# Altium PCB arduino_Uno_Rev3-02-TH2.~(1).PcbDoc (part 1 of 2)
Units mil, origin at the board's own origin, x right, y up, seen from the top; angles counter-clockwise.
Board outline 3492.03 x 2110.03 mil, 2 copper layers (Top Layer, Bottom Layer); 62 components, 73 nets, 317 pads, 77 vias.
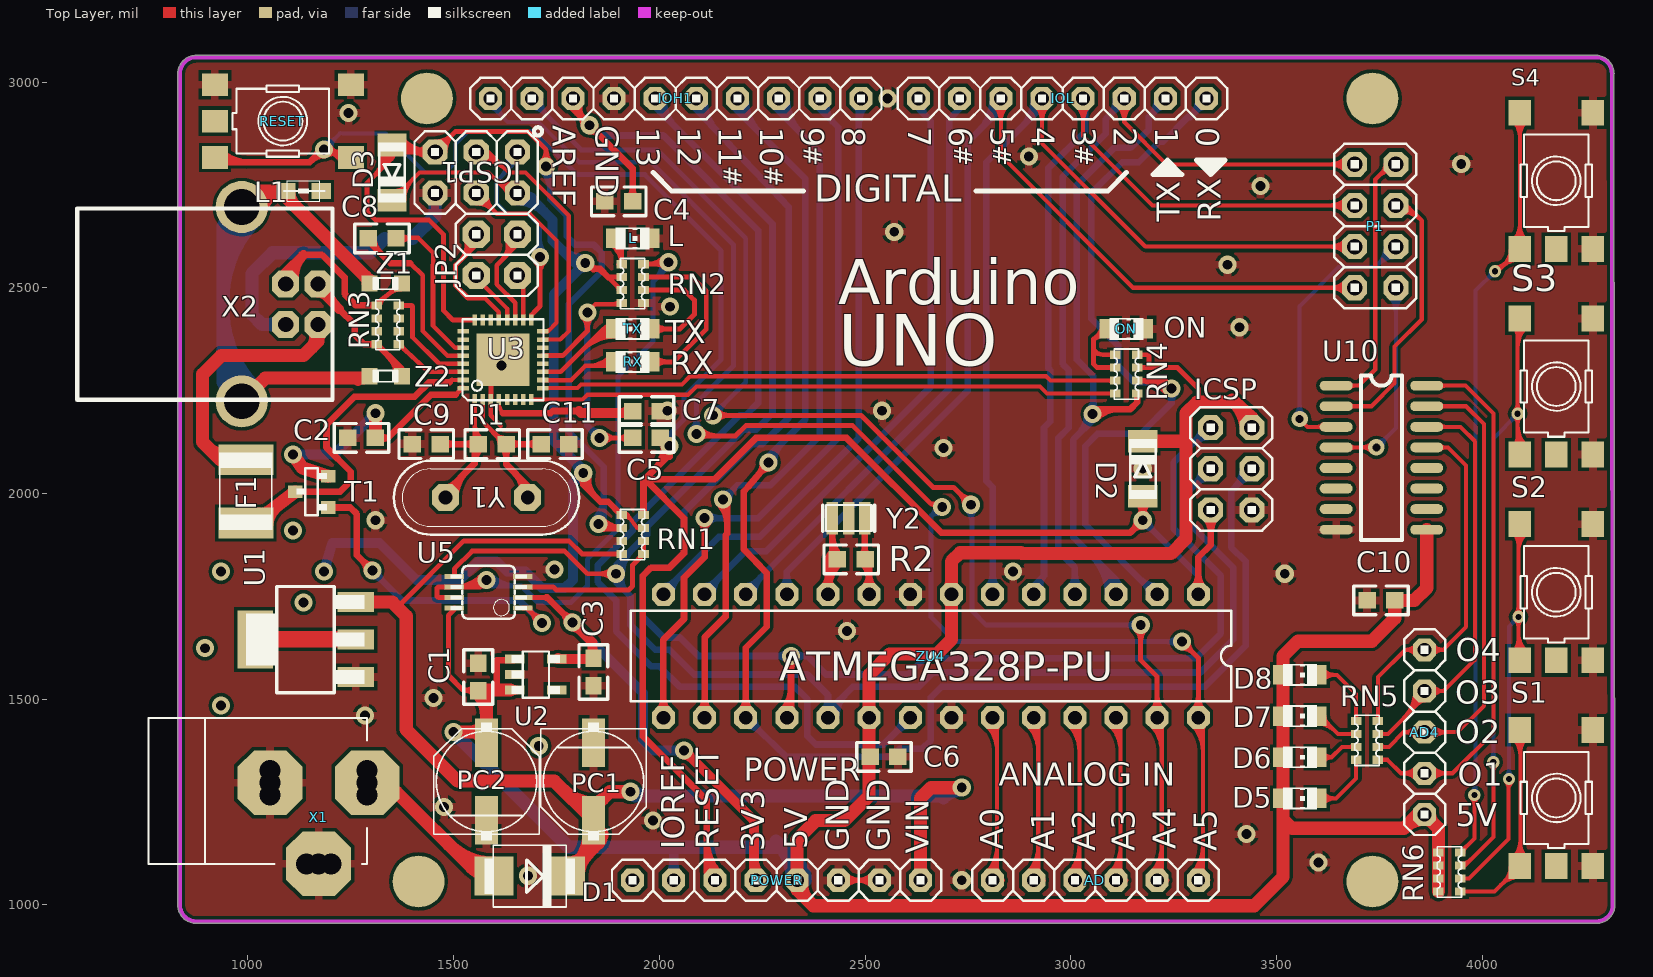
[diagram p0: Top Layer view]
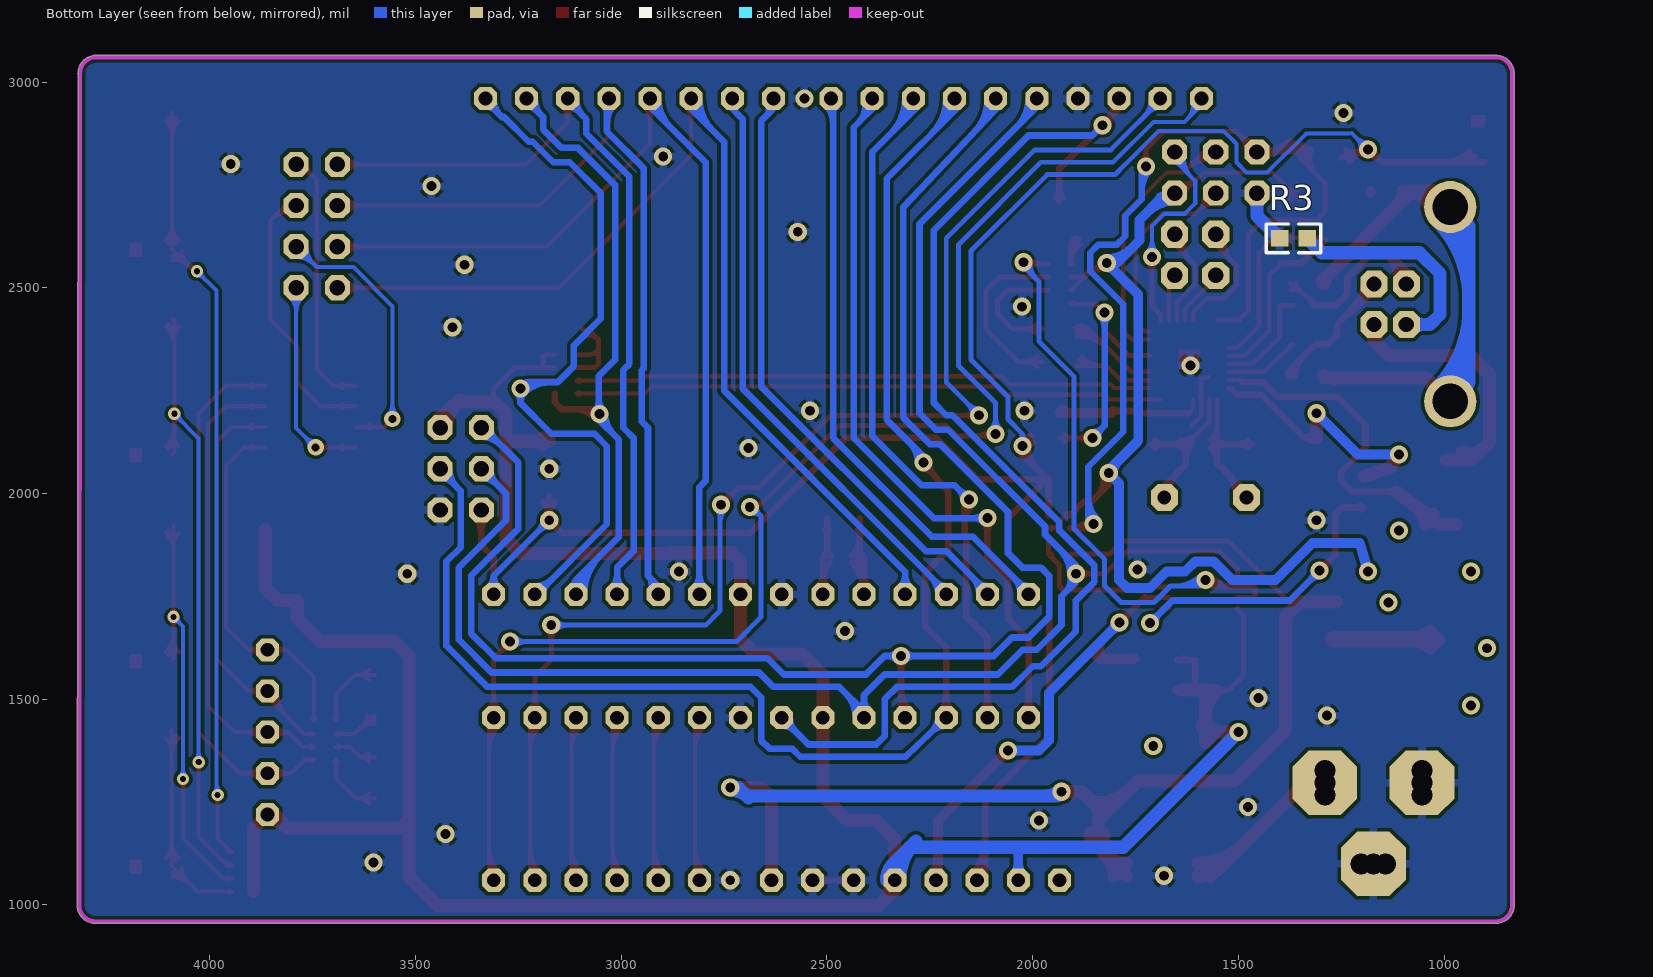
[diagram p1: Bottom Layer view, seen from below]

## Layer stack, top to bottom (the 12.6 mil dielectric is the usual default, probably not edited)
Top Layer: signal copper 1.4
Dielectric: dielectric 12.6, FR-4, Dk 4.8
Bottom Layer: signal copper 1.4

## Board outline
874.37,954.98 cw(c874.37,999.37) 829.98,999.37 cw(c835,999.37) 829.99,999.4 829.99,3020.63 829.98,3020.63 cw(c874.37,3020.63) 874.37,3065.02 cw(c874.37,3060) 874.4,3065.01 4277,3065.01 cw(c4277,3060) 4277.5,3064.99 cw(c4276,3020.63) 4320.39,3020.63 cw(c4315.37,3020.63) 4320.15,3019.11 4322.01,999.6 cw(c4317,999.37) 4322.02,999.37 cw(c4277.63,999.37) 4322.01,998.74 4322.02,994 cw(c4317,994) 4321.3,991.41 cw(c4277.63,999.37) 4277.63,954.98 cw(c4277.63,960) 4277.13,955.01 cw(c4276.63,960) 4276.63,954.99

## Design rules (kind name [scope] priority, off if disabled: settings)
Clearance [All] p1: gap=8
ComponentClearance [All] p1: gap=0 collisioncheckmode=3 verticalgap=0 showdistances=FALSE
FanoutControl Fanout_Small [All] p1 off: bgadir=Out bgaviamode=Centered fanoutstyle=Auto fanoutdirection=Alternating viagrid=1 // Protel DXP Scope 1 Expression Was: (CompPinCount < 5)   Fanout_Small (Default Rule)
FanoutControl Fanout_Default [All] p2: bgadir=Out bgaviamode=Centered fanoutstyle=Auto fanoutdirection=Alternating viagrid=1 // Fanout_Default (Default Rule)
FanoutControl Fanout_SOIC [All] p3 off: bgadir=Out bgaviamode=Centered fanoutstyle=Auto fanoutdirection=Alternating viagrid=1 // Protel DXP Scope 1 Expression Was: IsSOIC   Fanout_SOIC (Default Rule)
FanoutControl Fanout_BGA [All] p4 off: bgadir=Out bgaviamode=Centered fanoutstyle=Auto fanoutdirection=Alternating viagrid=1 // Protel DXP Scope 1 Expression Was: IsBGA   Fanout_BGA (Default Rule)
FanoutControl Fanout_LCC [All] p5 off: bgadir=Out bgaviamode=Centered fanoutstyle=Auto fanoutdirection=Alternating viagrid=1 // Protel DXP Scope 1 Expression Was: IsLCC   Fanout_LCC (Default Rule)
PolygonConnect [All] p1: connectstyle=Relief reliefconductorwidth=20 reliefentries=4 polygonreliefangle="90 Angle"
RoutingVias [All] p1: holewidth=28 width=50 viastyle="Through Hole" minholewidth=10 minwidth=20 maxholewidth=170 maxwidth=200
SilkscreenOverComponentPads [All] p1: minsilkscreentomaskgap=10
SolderMaskExpansion [All] p1: expansion=4
Width [All] p1: maxlimit=50 minlimit=10 preferedwidth=10
21 further rules are at their usual default settings.

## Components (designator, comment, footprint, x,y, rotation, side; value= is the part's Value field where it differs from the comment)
AD "6x1F-H8.5" 1X06 3060,1060 r0 top
AD4 "6x1F-H8.5" 1X05 3860,1420 r90 top
C1 "100n" R0603-ROUND 1560,1520 r90 top
C2 "100n" R0603-ROUND 1310,2135 r180 top
C3 "1u" R0603-ROUND 1840,1600 r270 top
C4 "100n" R0603-ROUND 1935,2710 r180 top
C5 "100n" R0603-ROUND 1935,2135 r0 top
C6 "100n" R0603-ROUND 2580,1360 r180 top
C7 "100n" R0603-ROUND 1935,2200 r0 top
C8 "1u" R0603-ROUND 1360,2620 r180 top
C9 "22p" R0603-ROUND 1400,2120 r0 top
C10 "0.1u" R0603-ROUND 3720,1740 r0 top
C11 "22p" R0603-ROUND 1780,2120 r180 top
D1 "M7" SMB 1685,1070 r180 top
D2 "CD1206-S01575" MINIMELF 3175,2060 r270 top
D3 "CD1206-S01575" MINIMELF 1350,2780 r90 top
D5 "YELLOW" CHIP-LED0805 3557,1259 r270 top
D6 "YELLOW" CHIP-LED0805 3557,1359 r270 top
D7 "YELLOW" CHIP-LED0805 3557,1459 r270 top
D8 "YELLOW" CHIP-LED0805 3557,1559 r270 top
F1 "MF-MSMF050-2 500mA" L1812 995,2005 r90 top
ICSP "3x2 M" 2X03 3390,2060 r270 top
ICSP1 "3x2 M" 2X03 1555,2780 r180 top
IOH1 "10x1F-H8.5" 1X10@1 2040,2960 r180 top
IOL "8x1F-H8.5" 1X08 2980,2960 r180 top
JP2 "2x2 M - NM" 2X02 1605,2580 r90 top
L "YELLOW" CHIP-LED0805 1935,2620 r270 top
L1 "BLM21" 0805 1135,2735 r180 top
ON "GREEN" CHIP-LED0805 3135,2400 r270 top
P1 "3x2 M" 2X04 3740,2700 r270 top
PC1 "47u" PANASONIC_D 1840,1300 r270 top
PC2 "47u" PANASONIC_D 1580,1300 r90 top
POWER "8x1F-H8.5" 1X08 2285,1060 r0 top
R1 "1M" R0603-ROUND 1560,2120 r0 top
R2 "1M" R0603-ROUND 2500,1840 r180 top
R3 "0R" R0603-ROUND 1400,2620 r180 bottom
RESET "TS42031-160R-TR-7260" TS42 1085,2905 r0 top
RN1 "10K" CAY16 1935,1900 r90 top
RN2 "1K" CAY16 1935,2510 r270 top
RN3 "22R" CAY16 1340,2410 r90 top
RN4 "1K" CAY16 3135,2290 r90 top
RN5 "1K" CAY16 3720,1400 r90 top
RN6 "10K" CAY16 3920,1080 r90 top
RX "YELLOW" CHIP-LED0805 1935,2320 r90 top
S1 "TS42031-160R-TR-7260" TS42 4180,1260 r90 top
S2 "TS42031-160R-TR-7260" TS42 4180,1760 r90 top
S3 "TS42031-160R-TR-7260" TS42 4180,2260 r90 top
S4 "TS42031-160R-TR-7260" TS42 4180,2760 r90 top
T1 "FDN340P" SOT-23 1155,2005 r270 top
TX "YELLOW" CHIP-LED0805 1935,2400 r90 top
U1 "NCP1117ST50T3G" SOT223 1140,1645 r90 top
U2 "LP2985-33DBVR" SOT23-DBV 1700,1560 r270 top
U3 "ATMEGA16U2-MU(R)" MLF32 1620,2325 r90 top
U5 "LMV358IDGKR" MSOP08 1585,1760 r90 top
U10 "ULN2003" sop16 3645,2262 r0 top
X1 "*" POWERSUPPLY_DC-21MM 1040,1300 r90 top
X2 "USB-B_TH" PN61729 985,2460 r270 top
Y1 "16MHz" QS 1580,1990 r180 top
Y2 "CSTCE16M0V53-R0 16MHZ" RESONATOR 2460,1940 r0 top
Z1 "CG0603MLC-05E" CT/CN0603 1335,2510 r180 top
Z2 "CG0603MLC-05E" CT/CN0603 1335,2285 r180 top
ZU4 "ATMEGA328P-PU" DIL28-3 2660,1605 r180 top

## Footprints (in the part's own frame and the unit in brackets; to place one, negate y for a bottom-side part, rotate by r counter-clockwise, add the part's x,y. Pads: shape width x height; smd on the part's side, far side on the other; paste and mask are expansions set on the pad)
1X05 [mil]
  oct 56x56 hole 33.46: 1(-200,0) 2(-100,0) 3(0,0) 4(100,0) 5(200,0)
  silkscreen extent -250,-50 250,50
1X06 [mil]
  oct 56x56 hole 33.46: 1(-250,0) 2(-150,0) 3(-50,0) 4(50,0) 5(150,0) 6(250,0)
  silkscreen extent -300,-50 300,50
1X08 [mil]
  oct 56x56 hole 33.46: 1(-350,0) 2(-250,0) 3(-150,0) 4(-50,0) 5(50,0) 6(150,0) 7(250,0) 8(350,0)
  silkscreen extent -400,-50 400,50
1X10@1 [mil]
  oct 56x56 hole 33.46: 1(-450,0) 2(-350,0) 3(-250,0) 4(-150,0) 5(-50,0) 6(50,0) 7(150,0) 8(250,0) 9(350,0) 10(450,0)
  silkscreen extent -500,-50 500,50
2X02 [mil]
  oct 66x66 hole 37.4: 1(-50,-50) 2(-50,50) 3(50,-50) 4(50,50)
  silkscreen extent -100,-100 100,100
2X03 [mm]
  oct 1.55x1.55 hole 0.95: 1(-2.54,-1.27) 2(-2.54,1.27) 3(0,-1.27) 4(0,1.27) 5(2.54,-1.27) 6(2.54,1.27)
  silkscreen extent -3.81,-2.54 3.81,2.54
2X04 [mm]
  oct 1.55x1.55 hole 0.95: 1(-2.54,-1.27) 2(-2.54,1.27) 3(0,-1.27) 4(0,1.27) 5(2.54,-1.27) 6(2.54,1.27) 7(5.08,-1.27) 8(5.08,1.27)
  silkscreen extent -3.81,-2.54 6.35,2.54
0805 [mm]
  rect 1.2x1 smd: 1(-1.1,0) 2(1.1,0)
  silkscreen extent -1.3,-0.63 1.2,0.63
CAY16 [mm]
  rect 0.5x0.65 smd: 1(-1.2,-0.675) 2(-0.4,-0.675) 3(0.4,-0.675) 4(1.2,-0.675) 5(1.2,0.675) 6(0.4,0.675) 7(-0.4,0.675) 8(-1.2,0.675)
  silkscreen extent -1.55,-0.75 1.55,0.75
CHIP-LED0805 [mm]
  rect 1.2x1.2 smd: A(0,-1.05) C(0,1.05)
  silkscreen extent -0.68,-1.05 0.68,1.05
CT/CN0603 [mm]
  rect 1x1 smd: 1(-1,0) 2(1,0)
  silkscreen extent -0.75,-0.35 0.75,0.35
DIL28-3 [mil]
  oct 56x56 hole 33.46: 1(-650,-150) 2(-550,-150) 3(-450,-150) 4(-350,-150) 5(-250,-150) 6(-150,-150) 7(-50,-150) 8(50,-150) 9(150,-150) 10(250,-150) 11(350,-150) 12(450,-150) 13(550,-150) 14(650,-150) 15(650,150) 16(550,150) 17(450,150) 18(350,150) 19(250,150) 20(150,150) 21(50,150) 22(-50,150) 23(-150,150) 24(-250,150) 25(-350,150) 26(-450,150) 27(-550,150) 28(-650,150)
  silkscreen extent -730,-110 730,110
L1812 [mm]
  rect 1.9x3.4 smd: 1(-1.95,0) 2(1.95,0)
  silkscreen extent -2.39,-1.65 2.4,1.65
MINIMELF [mm]
  rect 1.4x1.8 smd: A(1.7,0) C(-1.7,0)
  silkscreen extent -1.85,-0.86 1.85,0.86
MLF32 [mm]
  rect 0.7x0.28 smd: 1(-2.45,1.75) 2(-2.45,1.25) 3(-2.45,0.75) 4(-2.45,0.25) 5(-2.45,-0.25) 6(-2.45,-0.75) 7(-2.45,-1.25) 8(-2.45,-1.75) 17(2.45,-1.75) 18(2.45,-1.25) 19(2.45,-0.75) 20(2.45,-0.25) 21(2.45,0.25) 22(2.45,0.75) 23(2.45,1.25) 24(2.45,1.75)
  rect 0.28x0.7 smd: 9(-1.75,-2.45) 10(-1.25,-2.45) 11(-0.75,-2.45) 12(-0.25,-2.45) 13(0.25,-2.45) 14(0.75,-2.45) 15(1.25,-2.45) 16(1.75,-2.45) 25(1.75,2.45) 26(1.25,2.45) 27(0.75,2.45) 28(0.25,2.45) 29(-0.25,2.45) 30(-0.75,2.45) 31(-1.25,2.45) 32(-1.75,2.45)
  rect 3.254x3.254 smd: 33(0,0)
  Top Layer region: -0.635,-0.635 0.635,-0.635 0.635,0.635 -0.635,0.635
  silkscreen extent -2.5,-2.5 2.5,2.5
MSOP08 [mm]
  rect 0.3x1.2 smd: 1(-0.976,-2.113) 2(-0.326,-2.113) 3(0.324,-2.113) 4(0.974,-2.113) 5(0.974,2.112) 6(0.324,2.112) 7(-0.326,2.112) 8(-0.976,2.112)
  silkscreen extent -1.63,-2.36 1.62,2.36
PANASONIC_D [mm]
  rect 3x1.4 smd: +(2.4,0) -(-2.4,0)
  silkscreen extent -3.65,-3.25 3.65,3.25
PN61729 [mil]
  oct 66x66 hole 37.4: 1(49.21,185.43) 2(-49.21,185.43) 3(-49.21,106.69) 4(49.21,106.69)
  round 126.61 hole 86.61: P$1(-236.22,0) P$2(236.22,0)
  silkscreen extent -232,-400 232,220
POWERSUPPLY_DC-21MM [mm]
  oct 4x4 hole 1.3: 1(-5.08,-3.353) 2(-0.076,-6.35) 3(-0.076,-0.356)
  round 1.95 hole 1.3: 4(-5.08,-4.115) 5(-5.08,-2.591) 6(-0.838,-0.356) 7(0.686,-0.356) 8(-0.838,-6.35) 9(0.686,-6.35)
  silkscreen extent -5.08,-6.35 3.91,7.14
QS [mil]
  oct 66x66 hole 33.46: 1(-100,0) 2(100,0)
  silkscreen extent -225,-90 225,90
R0603-ROUND [mil]
  rect 42.5x40 smd: 1(0,0) 2(67.5,0)
  silkscreen extent -32,-35 100,35
RESONATOR [mm]
  rect 0.7x2 smd: 1(-1,0) 2(0,0) 3(1,0)
  silkscreen extent -1.6,-0.8 1.6,0.8
SMB [mm]
  rect 2.4x2.4 smd: A(2.2,0) C(-2.2,0)
  silkscreen extent -2.79,-1.91 2.79,1.91
sop16 [mil]
  oval 80x24 smd: 1(0,0) 2(0,-50) 3(0,-100) 4(0,-150) 5(0,-200) 6(0,-250) 7(0,-300) 8(0,-350) 9(220,-350) 10(220,-300) 11(220,-250) 12(220,-200) 13(220,-150) 14(220,-100) 15(220,-50) 16(220,0)
  silkscreen extent 60,-375 160,25
SOT23-DBV [mm]
  rect 0.55x1.2 smd: 1(-0.95,-1.3) 2(0,-1.3) 3(0.95,-1.3) 4(0.95,1.3) 5(-0.95,1.3)
  silkscreen extent -1.42,-1.5 1.42,1.5
SOT223 [mil]
  rect 48x88 smd: 1(-91,-122) 2(0,-122) 3(91,-122)
  rect 141.73x86.61 smd: 4(0,122.01)
  silkscreen extent -129,-144 129,144
SOT-23 [mil]
  rect 31x35 smd: 1(1,-40) 2(-37,40) 3(39,40)
  silkscreen extent -56,-37 58,37
TS42 [mm]
  rect 1.6x1.4 smd: 1(-4.2,2.25) 2(4.2,2.25) 3(-4.2,-2.25) 4(4.2,-2.25) 5(-4.2,0)
  Top Layer region: -4.699,-0.381 -3.81,-0.381 -3.81,0.381 -4.699,0.381
  silkscreen extent -3.1,-2.2 2.85,2.2

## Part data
AD: library part PINHD-1X6
AD4: library part PINHD-1X5
C1 C2 C3 C4 C5 C6 C7 C8 C9 C10 C11: library part C-EU0603-RND
D1: library part DIODE-SMB
D2 D3: library part DIODE-MINIMELF
D5 D6 D7 D8 L ON RX TX: library part LEDCHIP-LED0805
F1: library part L-EUL1812
ICSP ICSP1: library part PINHD-2X3
IOH1: library part PINHD-1X10_ARD
IOL POWER: library part PINHD-1X8
JP2: library part PINHD-2X2
L1: library part WE-CBF_0805
P1: library part PINHD-2X4
PC1 PC2: library part CPOL-EUD
R1 R2 R3: library part R-EU_R0603
RESET S1 S2 S3 S4: library part TS42
RN1 RN2 RN3 RN4 RN5 RN6: library part 4R-NCAY16
T1: library part PMOSSOT23
U1: library part MC33269ST-3.3T3
U2: library part LP2985-XXDBVR33
U3: library part ATMEGA16U2-MU
U5: library part LMV358MMX
X1: library part POWERSUPPLY_DC21MMX
X2: library part PN61729
Y1: library part XTAL/S
Y2: library part RESONATORMU
Z1 Z2: library part VARISTORCN0603

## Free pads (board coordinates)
  round 125.98 smd: ""(1415,1057) ""(1435,2960) ""(3733,1057) ""(3733,2960)

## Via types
v1: diameter 44, hole 24, Top Layer to Bottom Layer, 69 vias
v2: diameter 30, hole 15, Top Layer to Bottom Layer, 6 vias
v3: diameter 40, hole 20, Top Layer to Bottom Layer, 2 vias

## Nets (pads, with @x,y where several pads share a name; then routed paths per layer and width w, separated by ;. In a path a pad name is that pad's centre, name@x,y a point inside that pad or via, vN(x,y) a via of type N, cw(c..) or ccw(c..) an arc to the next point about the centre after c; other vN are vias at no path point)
+3V3: C3.1 POWER.4 U2.5 U5.2 | length 1499.4
  Top Layer w12: U5.2@1668.19,1747.17 1725.2,1747.17
  Top Layer w16: 1725.2,1747.17 1727.83,1747.17 v1(1789,1686) v1@1796.5,1678.5 ; v1@1775,1686 ccw(c1741.2,1686) 1765.1,1709.9 ccw(c1789,1733.8) v1@1789,1700
  Top Layer w24: U2.5@1753.78,1600 U2.5@1751.18,1597.4 1837.4,1597.4 1837.4,1637.6 v1(1789,1686) ; v1@1789,1676 cw(c1789,1651.86) 1806.07,1668.93 cw(c1823.14,1686) v1@1799,1686 ; 1817.43,1597.4 ccw(c1817.43,1621.32) C3.1@1834.34,1604.41 ; 1837.4,1626.84 ccw(c1865.59,1626.84) C3.1@1845.66,1606.91 ; v1@2060,1365 cw(c2060,1340.86) 2077.07,1357.93 cw(c2094.14,1375) v1@2070,1375 ; v1(2060,1375) 2230,1205 2230,1065 POWER.4@2235,1060 ; 2230,1110.7 ccw(c2285.7,1110.7) POWER.4@2246.31,1071.31
  Bottom Layer w24: v1@1789,1676 cw(c1789,1651.86) 1806.07,1668.93 cw(c1823.14,1686) v1@1799,1686 ; v1(1789,1686) 1960,1515 1960,1400 1985,1375 v1(2060,1375) ; v1@2052.93,1367.93 ccw(c2035.86,1350.86) 2035.86,1375 ccw(c2035.86,1399.14) v1@2052.93,1382.07
+5V: AD4.1 C1.1 C2.1 C6.2 C7.1 C10.2 D2.C D3.C D5.A D6.A D7.A D8.A ICSP1.2 ICSP.2 PC2.+ POWER.2 POWER.5 RN1.3 RN1.5 RN2.2 RN2.3 RN4.3 RN4.4 RN6.5 RN6.6 RN6.7 RN6.8 T1.2 U1.2 U1.4 U2.1 U2.3 U3.4 U3.32 U5.8 U10.9 ZU4.7 ZU4.20 | length 13469.7
  Top Layer w10: D3.C@1350,2713.07 1416.93,2780 1585,2780 1635,2730 ICSP1.2@1655,2730 ; D3.C@1357.87,2735.63 ccw(c1357.87,2771.08) 1382.94,2746.01 ; D3.C@1370.43,2713.07 cw(c1419.76,2713.07) 1384.88,2747.95 ; D3.C@1380.43,2713.07 cw(c1453.9,2713.07) 1401.95,2765.02 ; 1595,2770 ccw(c1635.56,2810.55) ICSP1.2@1649.01,2754.8 ; 1607.61,2757.39 ccw(c1640.46,2790.24) ICSP1.2@1651.36,2745.08 ; U3.4@1610.16,2228.54 1610.16,2209.84 1620,2195 ; U3.4@1610.66,2220.17 ccw(c1631.16,2216.02) 1613.73,2204.46 ; 1620.22,2744.78 ccw(c1645.36,2769.93) ICSP1.2@1653.71,2735.36 ; ICSP1.2@1625.59,2739.41 cw(c1616.18,2730) ICSP1.2@1629.49,2730 ; RN1.5@1910,1952.21 cw(c1913.38,1940.05) 1923.66,1947.38 ; RN1.5@1910.67,1945 RN1.5@1908.43,1947.24 1923.76,1947.24 1946.25,1915.75 RN1.3@1961.57,1915.75 ; RN1.5@1912.68,1942.57 cw(c1917.46,1925.41) 1931.96,1935.76 ; RN1.5@1914.81,1943.82 cw(c1923.07,1935.55) 1923.07,1947.24 cw(c1923.07,1958.93) RN1.5@1914.81,1950.66 ; RN1.3@1955.19,1912.33 ccw(c1946.93,1904.06) 1946.93,1915.75 ccw(c1946.93,1927.44) RN1.3@1955.19,1919.17
  Top Layer w12: U5.8@1501.85,1721.57 U5.8@1503.43,1720 ; U5.8@1503.42,1719.99 1487.5,1704.07 1487.5,1557.5 1523,1522 C1.1@1560,1522 ; 1505,2240 1521.1,2256.1 U3.32@1523.54,2256.1 ; 1511.98,2246.98 ccw(c1502.87,2256.1) U3.32@1515.76,2256.1 ; 1524.39,1522 cw(c1524.39,1485.64) C1.1@1550.1,1511.35 ; 1528.01,1522 ccw(c1528.01,1553.24) C1.1@1550.1,1531.15 ; RN2.3@1897.66,2503.84 cw(c1888.08,2494.25) RN2.3@1901.63,2494.25 ; RN2.3@1908.43,2494.25 1907.25,2494.25 1875.75,2525.75 RN2.2@1908.43,2525.75 ; RN4.3@3161.57,2305.75 3190,2305.75 ; RN4.4@3161.57,2337.24 3187.76,2337.24 3190,2335 3190,2305.75 ; 3310,2222 3310,2255 3259.25,2305.75 3190,2305.75
  Top Layer w16: C2.1@1310,2135 1340,2135 ; C2.1@1319.78,2126.56 cw(c1340,2106.56) 1340,2135 ; C2.1@1319.78,2143.44 ccw(c1340,2163.44) 1340,2135 ; 1505,2240 1445,2240 1340,2135 ; 1605,1522.6 1605,1595 1646.42,1595 U2.1@1648.82,1597.4 ; 1620,2195 1736.07,2195 1741.61,2200.54 1805,2200.54 ; 1623.41,1595 ccw(c1623.41,1610.02) U2.1@1634.03,1599.4 ; v1@1813.06,2050.5 ccw(c1850.16,2040.95) 1823.07,2013.86 ; v1(1815,2050) 1815,2021.93 ; v1@1818.65,2558.52 ccw(c1852,2595.2) 1854.36,2545.68 ; v1(1820,2560) 1840,2545 1855.75,2545.75 1875.75,2525.75 ; v1@1828.56,2046.51 ccw(c1881.69,2032.83) 1842.89,1994.04 ; RN1.5@1908.43,1947.24 1875.67,1980 1856.93,1980 1815,2021.93 ; C6.2@2502.4,1367.4 C6.2@2510,1360 ; 1815,2021.93 cw(c1836.14,2021.93) 1823.42,2038.82 ccw(c1836.14,2021.93) 1815,2021.93 ; 1815,2021.93 ccw(c1793.86,2021.93) 1806.58,2038.82 cw(c1793.86,2021.93) 1815,2021.93
  Top Layer w20: U1.2@1262,1645 U1.2@1269,1646 ; ICSP.2@3435,2160 ICSP.2@3440,2160
  Top Layer w24: U2.3@1637.6,1522.6 U2.3@1648.82,1522.6 ; 1805,2200.54 1810,2195.54 C7.1@1935,2195.54 ; 1903.67,2195.54 ccw(c1903.67,2230.08) C7.1@1928.09,2205.66 ; C6.2@2510,1370 2511.54,1388.46 2510,1410 ; C6.2@2505.2,1365.24 ccw(c2484.62,1383.07) 2511.79,1385.01 cw(c2484.62,1383.07) C6.2@2505.2,1365.24
  Top Layer w32: v1(1110,2095) 1133,2062 T1.2@1195,2042 ; C2.1@1310,2135 v1(1310,2195) ; v1(1500,1420) 1554.49,1420 PC2.+@1580,1394.49 1580,1500 C1.1@1560,1520 1562.6,1522.6 1605,1522.6 U2.3@1637.6,1522.6 ; 1537.64,1420 ccw(c1537.64,1468.34) 1571.83,1434.16 ccw(c1552.09,1453.89) 1580,1453.89 ccw(c1607.91,1453.89) PC2.+@1588.17,1434.16 ; C1.1@1557.17,1515.92 cw(c1502.06,1460.81) 1580,1460.81 ; POWER.5@2326.51,1068.49 ccw(c2306.03,1088.97) 2335,1088.97 ccw(c2363.97,1088.97) POWER.5@2343.49,1068.49 ; POWER.5@2346.84,1058.07 ccw(c2402.06,1049.06) 2362.5,1009.5 ; ZU4.20@2501.51,1446.51 cw(c2481.03,1426.03) 2510,1426.03 cw(c2538.97,1426.03) ZU4.20@2518.49,1446.51 ; ZU4.20@2501.51,1463.49 ccw(c2481.03,1483.97) 2510,1483.97 ccw(c2538.97,1483.97) ZU4.20@2518.49,1463.49 ; ZU4.7@2701.51,1746.51 cw(c2681.03,1726.03) 2710,1726.03 cw(c2738.97,1726.03) ZU4.7@2718.49,1746.51 ; ZU4.7@2701.51,1763.49 ccw(c2681.03,1783.97) 2710,1783.97 ccw(c2738.97,1783.97) ZU4.7@2718.49,1763.49 ; D2.C@3175,2126.93 3273.07,2126.93 3280,2120 ; D2.C@3191.05,2118.76 cw(c3210.78,2099.02) 3210.78,2126.93 cw(c3210.78,2154.84) D2.C@3191.05,2135.1 ; 3392.13,2227.17 cw(c3326.63,2152.82) ICSP.2@3425.52,2159.08 ; ICSP.2@3440,2158.54 ICSP.2@3440,2160 3440,2185 3398,2222 3310,2222 3307,2222 3280,2195 3280,2120 ; 3811.23,1187.8 cw(c3860,1139.03) 3860,1208 cw(c3860,1179.03) 3880.49,1199.51 cw(c3900.97,1220) AD4.1@3872,1220 ; U10.9@3865,1912 3865,1770 3835,1740 C10.2@3787.5,1740 3787.5,1696.5 3732,1641 3552,1641 3515.66,1604.66 D8.A@3515.66,1559 D7.A@3515.66,1459 D6.A@3515.66,1359 D5.A@3515.66,1259 3515.66,1208.34 ; RN6.8@3893.43,1032.76 RN6.7@3893.43,1064.25 RN6.6@3893.43,1095.75 RN6.5@3893.43,1127.24 3893.43,1186.57 AD4.1@3860,1220 3843.43,1220 3810,1186.57 3537.43,1186.57 3515.66,1208.34 ; 3280,2120 3280,1890 3244,1854 2881.05,1854 2879.05,1856 2731,1856 2710,1835 ZU4.7@2710,1755 2710,1645 2675,1610 2560,1610 2510,1560 ZU4.20@2510,1455 2510,1410 2510,1370 2510,1360 2510,1265 2450,1205 2380,1205 2335,1160 POWER.5@2335,1060 2335,1037 2374,998 3446,998 3515.66,1067.66 3515.66,1208.34
  Top Layer w40: U1.4@1017.99,1645 1065,1645 ; U1.4@1034.47,1628.52 cw(c1076.67,1586.32) 1076.67,1646 ; U1.4@1034.47,1661.48 ccw(c1071.84,1698.85) 1071.84,1646 ; U1.4@1035.8,1660.03 ccw(c1066,1685.5) 1066,1646 ; U1.4@1036.54,1630.89 cw(c1065,1609.25) 1065,1645 ; U1.4@1036.54,1659.11 ccw(c1065,1680.75) 1065,1645 ; U1.4@1036.78,1631.2 cw(c1066,1609.75) 1066,1646 ; U1.2@1269,1646 1066,1646 ; 1065,1645 1066,1646
  Bottom Layer w24: v1(1110,2095) 1210,2095 v1(1310,2195) ; v1@1117.07,2087.93 cw(c1134.14,2070.86) 1134.14,2095 cw(c1134.14,2119.14) v1@1117.07,2102.07 ; v1@1180.14,1818.74 ccw(c1168.42,1839.85) 1191.63,1833.21 ccw(c1214.85,1826.58) v1@1193.74,1814.86 ; v1(1185,1810) 1205,1880 1320,1880 1410,1790 1515,1790 1560,1835 1605,1835 1630,1810 1675,1810 1715,1770 1770,1770 1790,1790 1790,2025 v1(1815,2050) 1815,2056.6 1743.3,2128.3 1743.3,2483.3 v1(1820,2560) 1795,2560 1740,2615 1740,2665 1690,2715 1690,2720 ; v1@1300,2195 cw(c1275.86,2195) 1292.93,2177.93 cw(c1310,2160.86) v1@1310,2185 ; ICSP1.2@1655,2711.49 cw(c1655,2618.51) 1720.74,2684.26 ; ICSP1.2@1655,2730 1665,2720 1690,2720 ; ICSP1.2@1661.88,2712.82 cw(c1675.02,2680.02) 1700,2705 ; ICSP1.2@1673.13,2733.74 ccw(c1690,2737.22) 1690,2720 ; 1760.25,2594.75 ccw(c1820,2654.5) v1@1820,2570 ; 1793.26,2078.34 cw(c1764.92,2050) v1@1805,2050 ; v1@1810,2560 cw(c1785.86,2560) 1802.93,2542.93 cw(c1820,2525.86) v1@1820,2550 ; POWER.2@2023.69,1071.31 ccw(c1996.37,1098.63) 2035,1098.63 ccw(c2073.63,1098.63) POWER.2@2046.31,1071.31 ; POWER.2@2035,1060 2035,1140 2035,1145 2040,1140
  Bottom Layer w32: v1(1500,1420) 1780,1140 2035,1140 2040,1140 2299,1140 2336,1103 POWER.5@2335,1060 ; 2283.4,1155.6 cw(c2187.8,1060) POWER.5@2323,1060 ; POWER.5@2326.71,1068.68 ccw(c2306.71,1089.64) 2335.67,1088.96 ccw(c2364.64,1088.29) POWER.5@2343.68,1068.29 ; 2338.03,1100.97 cw(c2297.06,1060) POWER.5@2355,1060
  other v1: 1707,1386 935,1485 896,1624 1135,1735 935,1810 1110,1910
AD0: AD.1 RN6.1 S1.1 S1.2 ZU4.23 | length 1621.2
  Top Layer w10: AD.1@2793.74,1076.26 ccw(c2727.92,1142.08) 2821,1142.08 ; ZU4.23@2793.74,1438.74 cw(c2727.92,1372.92) 2821,1372.92 ; AD.1@2800.81,1069.19 ccw(c2752.06,1117.94) 2821,1117.94 ; ZU4.23@2800.81,1445.81 cw(c2752.06,1397.06) 2821,1397.06 ; AD.1@2807.88,1062.12 ccw(c2776.2,1093.8) 2821,1093.8 ; ZU4.23@2807.88,1452.88 cw(c2776.2,1421.2) 2821,1421.2 ; ZU4.23@2810,1455 2821,1439 2821,1078 AD.1@2835,1060 ; 2821,1088.97 ccw(c2838.97,1088.97) AD.1@2826.26,1076.26 ; 2821,1426.03 cw(c2838.97,1426.03) ZU4.23@2826.26,1438.74 ; RN6.1@3946.57,1032.76 4029.53,1032.76 S1.1@4091.42,1094.65 4093,1096.23 4093,1423.77 S1.2@4091.42,1425.35 ; RN6.1@3952.95,1029.34 cw(c3961.21,1021.07) 3961.21,1032.76 cw(c3961.21,1044.45) RN6.1@3952.95,1036.18 ; 4046.19,1049.41 cw(c4091.42,1004.18) S1.1@4091.42,1068.15 ; 4055.69,1058.92 ccw(c4023.9,1090.71) S1.1@4068.86,1090.71 ; 4063.26,1066.49 cw(c4091.42,1038.33) S1.1@4091.42,1078.15 ; S1.1@4075.47,1114.53 ccw(c4033.14,1156.86) 4093,1156.86 ; S1.2@4075.47,1405.46 cw(c4033.14,1363.14) 4093,1363.14 ; S1.1@4082.54,1107.46 ccw(c4057.29,1132.72) 4093,1132.72 ; S1.2@4082.54,1412.53 cw(c4057.29,1387.28) 4093,1387.28 ; 4093,1149.23 ccw(c4142.07,1149.23) S1.1@4107.37,1114.53 ; 4093,1370.77 cw(c4142.07,1370.77) S1.2@4107.37,1405.46
AD1: AD.2 RN6.2 S2.1 S2.2 ZU4.24 | length 2241.9
  Top Layer w10: AD.2@2893.74,1076.26 ccw(c2827.92,1142.08) 2921,1142.08 ; ZU4.24@2893.74,1438.74 cw(c2827.92,1372.92) 2921,1372.92 ; AD.2@2900.81,1069.19 ccw(c2852.06,1117.94) 2921,1117.94 ; ZU4.24@2900.81,1445.81 cw(c2852.06,1397.06) 2921,1397.06 ; AD.2@2907.88,1062.12 ccw(c2876.2,1093.8) 2921,1093.8 ; ZU4.24@2907.88,1452.88 cw(c2876.2,1421.2) 2921,1421.2 ; ZU4.24@2910,1455 2921,1439 2921,1078 AD.2@2935,1060 ; 2921,1088.97 ccw(c2938.97,1088.97) AD.2@2926.26,1076.26 ; 2921,1426.03 cw(c2938.97,1426.03) ZU4.24@2926.26,1438.74 ; RN6.2@3946.57,1064.25 3968.25,1064.25 4064,1160 4064,1307 v2(4065,1306) ; RN6.2@3952.95,1060.83 cw(c3961.21,1052.56) 3961.21,1064.25 cw(c3961.21,1075.94) RN6.2@3952.95,1067.67 ; v2@4057.93,1298.93 cw(c4043.27,1284.27) 4064,1284.27 ; 4064,1279.44 cw(c4091.56,1279.44) v2@4072.07,1298.93 ; S2.1@4075.47,1614.53 ccw(c4045.21,1644.79) 4088,1644.79 ; S2.2@4075.47,1905.46 cw(c4045.21,1875.21) 4088,1875.21 ; v2@4080.93,1692.93 cw(c4063.86,1675.86) 4088,1675.86 cw(c4112.14,1675.86) v2@4095.07,1692.93 ; v2@4080.93,1707.07 ccw(c4063.86,1724.14) 4088,1724.14 ccw(c4112.14,1724.14) v2@4095.07,1707.07 ; 4088,1637.16 ccw(c4130,1637.16) S2.1@4100.3,1607.46 ; 4088,1661.3 ccw(c4154.14,1661.3) S2.1@4107.37,1614.53 ; 4088,1858.69 cw(c4154.14,1858.69) S2.2@4107.37,1905.46 ; 4088,1882.84 cw(c4130,1882.84) S2.2@4100.3,1912.53 ; S2.2@4088,1921.93 v2(4088,1700) 4088,1598.07 S2.1@4091.42,1594.65
  Bottom Layer w10: v2@4057.93,1313.07 ccw(c4040.86,1330.14) 4065,1330.14 ccw(c4089.14,1330.14) v2@4072.07,1313.07 ; v2@4063,1304 v2(4065,1306) 4065,1677 v2(4088,1700) ; v2@4078,1700 cw(c4053.86,1700) 4070.93,1682.93 cw(c4088,1665.86) v2@4088,1690
AD2: AD.3 RN6.3 S3.1 S3.2 ZU4.25 | length 2715.3
  Top Layer w10: AD.3@2993.74,1076.26 ccw(c2927.92,1142.08) 3021,1142.08 ; ZU4.25@2993.74,1438.74 cw(c2927.92,1372.92) 3021,1372.92 ; AD.3@3000.81,1069.19 ccw(c2952.06,1117.94) 3021,1117.94 ; ZU4.25@3000.81,1445.81 cw(c2952.06,1397.06) 3021,1397.06 ; AD.3@3007.88,1062.12 ccw(c2976.2,1093.8) 3021,1093.8 ; ZU4.25@3007.88,1452.88 cw(c2976.2,1421.2) 3021,1421.2 ; ZU4.25@3010,1455 3021,1439 3021,1078 AD.3@3035,1060 ; 3021,1088.97 ccw(c3038.97,1088.97) AD.3@3026.26,1076.26 ; 3021,1426.03 cw(c3038.97,1426.03) ZU4.25@3026.26,1438.74 ; RN6.3@3946.57,1095.75 3957.75,1095.75 4027,1165 v2@4027,1346 ; RN6.3@3949.52,1100.59 ccw(c3949.52,1132.15) 3971.83,1109.83 ; v2@4019.93,1339.93 cw(c4002.86,1322.86) 4027,1322.86 cw(c4051.14,1322.86) v2@4034.07,1339.93 ; S3.1@4075.47,2114.53 ccw(c4050.04,2139.96) 4086,2139.96 ; S3.2@4075.47,2405.46 cw(c4050.04,2380.04) 4086,2380.04 ; v2@4078.93,2186.93 cw(c4061.86,2169.86) 4086,2169.86 cw(c4110.14,2169.86) v2@4093.07,2186.93 ; v2@4078.93,2201.07 ccw(c4061.86,2218.14) 4086,2218.14 ccw(c4110.14,2218.14) v2@4093.07,2201.07 ; 4086,2141.99 ccw(c4134.83,2141.99) S3.1@4100.3,2107.46 ; 4086,2166.13 ccw(c4158.97,2166.13) S3.1@4107.37,2114.53 ; 4086,2353.87 cw(c4158.97,2353.87) S3.2@4107.37,2405.46 ; 4086,2378.01 cw(c4134.83,2378.01) S3.2@4100.3,2412.53 ; S3.1@4091.42,2094.65 4086,2100.07 v2(4086,2194) 4086,2419.93 S3.2@4091.42,2425.35
  Bottom Layer w10: v2@4019.93,1354.07 ccw(c4002.86,1371.14) 4027,1371.14 ccw(c4051.14,1371.14) v2@4034.07,1354.07 ; v2(4027,1347) 4027,2134 4086,2193 v2(4086,2194) ; 4068.22,2175.22 ccw(c4049.44,2194) v2@4076,2194 ; 4070.64,2177.64 cw(c4086,2162.27) v2@4086,2184
AD3: AD.4 RN6.4 S4.1 S4.2 ZU4.26 | length 3158.2
  Top Layer w10: AD.4@3093.74,1076.26 ccw(c3027.92,1142.08) 3121,1142.08 ; ZU4.26@3093.74,1438.74 cw(c3027.92,1372.92) 3121,1372.92 ; AD.4@3100.81,1069.19 ccw(c3052.06,1117.94) 3121,1117.94 ; ZU4.26@3100.81,1445.81 cw(c3052.06,1397.06) 3121,1397.06 ; AD.4@3107.88,1062.12 ccw(c3076.2,1093.8) 3121,1093.8 ; ZU4.26@3107.88,1452.88 cw(c3076.2,1421.2) 3121,1421.2 ; ZU4.26@3110,1455 3121,1439 3121,1078 AD.4@3135,1060 ; 3121,1088.97 ccw(c3138.97,1088.97) AD.4@3126.26,1076.26 ; 3121,1426.03 cw(c3138.97,1426.03) ZU4.26@3126.26,1438.74 ; RN6.4@3946.57,1127.24 3981,1161.67 v2(3981,1267) ; RN6.4@3954.37,1127.24 cw(c3973.18,1127.24) 3959.88,1140.55 ; v2@3973.93,1259.93 cw(c3956.86,1242.86) 3981,1242.86 cw(c4005.14,1242.86) v2@3988.07,1259.93 ; v2(4031,2540) 4036.77,2540 S4.1@4091.42,2594.65 S4.2@4091.42,2925.35 ; v2@4031,2550 ccw(c4031,2588.08) 4057.93,2561.15 ; 4046.19,2549.41 cw(c4091.42,2504.18) S4.1@4091.42,2568.15 ; 4055.69,2558.92 ccw(c4023.9,2590.71) S4.1@4068.86,2590.71 ; 4063.26,2566.49 cw(c4091.42,2538.33) S4.1@4091.42,2578.15 ; S4.1@4075.47,2614.53 ccw(c4036.96,2653.05) 4091.42,2653.05 ccw(c4145.88,2653.05) S4.1@4107.37,2614.53 ; S4.2@4075.47,2905.46 cw(c4036.96,2866.95) 4091.42,2866.95 cw(c4145.88,2866.95) S4.2@4107.37,2905.46 ; S4.1@4082.54,2607.46 ccw(c4061.1,2628.9) 4091.42,2628.9 ccw(c4121.74,2628.9) S4.1@4100.3,2607.46 ; S4.2@4082.54,2912.53 cw(c4061.1,2891.09) 4091.42,2891.09 cw(c4121.74,2891.09) S4.2@4100.3,2912.53
  Bottom Layer w10: v2@3973.93,1274.07 ccw(c3949.62,1298.38) 3984,1298.38 ; v2@3984,1267 3984,2493 v2(4031,2540) ; 3984,1283.9 ccw(c3997.9,1283.9) v2@3988.07,1274.07 ; v2@4021,2540 cw(c3996.86,2540) 4013.93,2522.93 cw(c4031,2505.86) v2@4031,2530
AD4/SDA: AD.5 IOH1.9 ZU4.27 | length 4104.7
  Top Layer w10: AD.5@3193.74,1076.26 ccw(c3127.92,1142.08) 3221,1142.08 ; ZU4.27@3193.74,1438.74 cw(c3127.92,1372.92) 3221,1372.92 ; AD.5@3200.81,1069.19 ccw(c3152.06,1117.94) 3221,1117.94 ; ZU4.27@3200.81,1445.81 cw(c3152.06,1397.06) 3221,1397.06 ; AD.5@3207.88,1062.12 ccw(c3176.2,1093.8) 3221,1093.8 ; ZU4.27@3207.88,1452.88 cw(c3176.2,1421.2) 3221,1421.2 ; ZU4.27@3210,1455 3221,1439 3221,1078 AD.5@3235,1060 ; 3221,1088.97 ccw(c3238.97,1088.97) AD.5@3226.26,1076.26 ; 3221,1426.03 cw(c3238.97,1426.03) ZU4.27@3226.26,1438.74
  Top Layer w12: v1(2130,2190) 2490,2190 2665,2015 2715,2015 v1(2757.5,1972.5) v1@2765,1970 ; v1@2141.31,2178.69 cw(c2168.63,2151.37) 2168.63,2190 cw(c2168.63,2228.63) v1@2141.31,2201.31 ; v1@2741.5,1972.5 ccw(c2702.87,1972.5) 2730.19,1999.81 ccw(c2757.5,2027.13) v1@2757.5,1988.5 ; v1@3158.69,1668.69 cw(c3131.37,1641.37) 3170,1641.37 cw(c3208.63,1641.37) v1@3181.31,1668.69 ; v1(3170,1680) 3170,1595 3210,1555 ZU4.27@3210,1455 ; ZU4.27@3194.44,1470.56 ccw(c3156.89,1508.11) 3210,1508.11 ccw(c3263.11,1508.11) ZU4.27@3225.56,1470.56
  Bottom Layer w12: IOH1.9@1675,2960 1685,2960 1810,2835 1995,2835 2210,2620 2210,2270 v1(2130,2190) ; IOH1.9@1690,2938 cw(c1690,2896.96) 1719.02,2925.98 ; IOH1.9@1700,2960 ccw(c1736.21,2960) 1710.61,2934.39 ; IOH1.9@1712,2960 ccw(c1777.18,2960) 1731.09,2913.91 ; v1@2130,2206 ccw(c2130,2244.63) 2157.31,2217.31 ccw(c2184.63,2190) v1@2146,2190 ; v1@2746.19,1961.19 cw(c2712.84,1927.84) 2760,1927.84 ; v1(2757.5,1972.5) 2760,1970 2760,1715 2795,1680 v1(3170,1680) ; 2760,1939.91 cw(c2790.09,1939.91) v1@2768.81,1961.19 ; v1@3158.69,1668.69 ccw(c3131.37,1641.37) 3131.37,1680 ccw(c3131.37,1718.63) v1@3158.69,1691.31
AD5/SCL: AD.6 IOH1.10 ZU4.28 | length 4332.1
  Top Layer w10: AD.6@3293.74,1076.26 ccw(c3227.92,1142.08) 3321,1142.08 ; ZU4.28@3293.74,1438.74 cw(c3227.92,1372.92) 3321,1372.92 ; AD.6@3300.81,1069.19 ccw(c3252.06,1117.94) 3321,1117.94 ; ZU4.28@3300.81,1445.81 cw(c3252.06,1397.06) 3321,1397.06 ; AD.6@3307.88,1062.12 ccw(c3276.2,1093.8) 3321,1093.8 ; ZU4.28@3307.88,1452.88 cw(c3276.2,1421.2) 3321,1421.2 ; ZU4.28@3310,1455 3321,1439 3321,1301 3321,1078 AD.6@3335,1060 ; 3321,1088.97 ccw(c3338.97,1088.97) AD.6@3326.26,1076.26 ; 3321,1426.03 cw(c3338.97,1426.03) ZU4.28@3326.26,1438.74
  Top Layer w12: v1(2090,2145) 2090,2140 2185,2140 2210,2165 2470,2165 2660,1975 ; v1@2092.83,2147.83 ccw(c2111.73,2166.73) 2111.73,2140 ; v1@2101.31,2133.69 cw(c2116.56,2118.44) 2116.56,2140 ; v1@2101.31,2156.31 ccw(c2140.7,2195.7) 2140.7,2140 ; v1@2671.7,1965.01 ccw(c2660,1963.16) 2660,1975 ; v1(2687.5,1967.5) 2680,1975 2660,1975 ; v1@3270,1624 cw(c3270,1585.37) 3297.31,1612.69 cw(c3324.63,1640) v1@3286,1640 ; v1(3270,1640) 3310,1600 ZU4.28@3310,1455 ; ZU4.28@3294.44,1470.56 ccw(c3256.89,1508.11) 3310,1508.11 ccw(c3363.11,1508.11) ZU4.28@3325.56,1470.56
  Bottom Layer w10: IOH1.10@1575,2960 1631,2903 1706,2903 1805,2805 ; IOH1.10@1589.8,2937 cw(c1589.63,2918.01) 1603.18,2931.32 ; IOH1.10@1602.53,2956.55 ccw(c1635.85,2947.37) 1611.2,2923.15 ; IOH1.10@1612.17,2953.89 ccw(c1655.2,2942.05) 1623.37,2910.77
  Bottom Layer w12: 1805,2805 1980,2805 2180,2605 2180,2310 2090,2220 v1(2090,2145) ; v1@2078.69,2156.31 ccw(c2051.37,2183.63) 2090,2183.63 ccw(c2128.63,2183.63) v1@2101.31,2156.31 ; v1@2671.51,1968.12 cw(c2640.09,1969.34) 2660,1945 ; v1@2684.94,1951.71 ccw(c2679.92,1920.66) 2660,1945 ; v1(2687.5,1967.5) 2660,1945 ; v1@3258.69,1628.69 ccw(c3231.37,1601.37) 3231.37,1640 ccw(c3231.37,1678.63) v1@3258.69,1651.31 ; v1(3270,1640) 2720,1640 2660,1700 2660,1945
AREF: C4.1 IOH1.8 ZU4.21 | length 3217.2
  Top Layer w16: IOH1.8@1775,2960 1775,2950 v1(1830,2895) 1935,2790 C4.1@1935,2710 ; IOH1.8@1793.7,2958.48 ccw(c1822.62,2946.6) 1800.51,2924.49 ; IOH1.8@1808.5,2952.4 ccw(c1846.7,2936.71) v1@1817.5,2907.5 ; v1@1816,2895 ccw(c1782.2,2895) 1806.1,2918.9 ccw(c1830,2942.8) v1@1830,2909 ; v1@1830,2881 cw(c1830,2847.2) 1853.9,2871.1 cw(c1877.8,2895) v1@1844,2895 ; C4.1@1926.51,2718.49 ccw(c1906.03,2738.97) 1935,2738.97 ccw(c1963.97,2738.97) C4.1@1943.49,2718.49
  Bottom Layer w16: v1(1830,2895) 1855,2870 2010,2870 2240,2640 2240,2220 2210,2190 2195,2190 1935,1930 1935,1910 1850,1825 1850,1785 1895,1740 1895,1665 1980,1580 2000,1580 2050,1530 2330,1530 2360,1500 2360,1410 2380,1390 2545,1390 ZU4.21@2610,1455 ; ZU4.21@2590,1455 cw(c2541.72,1455) 2575.86,1420.86 cw(c2610,1386.72) ZU4.21@2610,1435
CMP: RN1.1 RN1.2 U5.3 | length 407.3
  Top Layer w12: U5.3@1668.19,1772.76 1742.24,1772.76 1750,1765 1925,1765 1935,1775 1935,1826.18 RN1.1@1961.57,1852.76 RN1.2@1961.57,1884.25 ; 1949.97,1841.16 ccw(c1938.37,1852.76) RN1.1@1954.77,1852.76
D+: RN3.5 X2.3 Z1.1 | length 615.2
  Top Layer w12: RN3.5@1313.43,2457.24 1311.18,2460 Z1.1@1374.37,2510 ; RN3.5@1320.2,2456.8 cw(c1347.7,2453.59) 1330.52,2475.3 ; Z1.1@1360.78,2511.58 cw(c1327.96,2515.41) 1348.46,2489.5 cw(c1368.96,2463.59) Z1.1@1372.79,2496.41
  Top Layer w16: 1135,2580 1180,2580 1235,2525 1235,2485 1262.76,2457.24 RN3.5@1313.43,2457.24
  Top Layer w24: X2.3@1088.72,2508.78 cw(c1132.2,2515.07) 1101.13,2546.13 ; X2.3@1091.69,2509.21 1091.69,2536.69 1135,2580 ccw(c1191.36,2523.63) X2.3@1112.47,2512.22
  Bottom Layer w24: X2.3@1090.91,2510 X2.3@1091.69,2509.21
D-: RN3.8 X2.2 Z2.1 | length 553.7
  Top Layer w16: 1221.54,2448.46 1260,2410 1260,2385 1282.24,2362.76 RN3.8@1313.43,2362.76 1366.18,2310 ; 1342.54,2333.64 cw(c1293.9,2285.01) Z2.1@1362.68,2285 ; 1357.78,2318.4 cw(c1338.96,2299.59) Z2.1@1363.57,2289.45 ; Z2.1@1364.23,2290.8 ccw(c1343.59,2302.6) 1366.18,2310 ; 1369.85,2306.33 cw(c1348.53,2285) Z2.1@1378.68,2285 ; Z2.1@1374.37,2285 1366.18,2310 ; Z2.1@1379.12,2295.68 cw(c1388.77,2317.4) 1366.18,2310
  Top Layer w24: X2.2@1170.43,2488.21 cw(c1170.43,2460.78) X2.2@1189.82,2480.18 ; X2.2@1170.43,2509.21 1170.79,2499.21 1221.54,2448.46 ; X2.2@1191.43,2509.21 ccw(c1265.4,2509.21) 1213.1,2456.9
  Bottom Layer w12: X2.2@1170,2509.65 X2.2@1170.43,2509.21
GATE_CMD: T1.3 U5.1 | length 1029.9
  Top Layer w12: U5.1@1668.19,1721.57 1678.43,1721.57 v1(1715,1685) ; U5.1@1685.81,1721.57 ccw(c1703.63,1721.57) 1691.03,1708.97 ; v1@1699,1685 ccw(c1660.37,1685) 1687.69,1712.31 ccw(c1715,1739.63) v1@1715,1701
  Top Layer w16: T1.3@1195,1966 1249,1966 1265,1950 1265,1850 1292.5,1822.5 v1(1302.5,1812.5) v1@1310,1805 ; T1.3@1202.3,1960.7 cw(c1215.11,1947.89) 1215.11,1966 cw(c1215.11,1984.11) T1.3@1202.3,1971.3 ; v1@1288.5,1812.5 ccw(c1254.7,1812.5) 1278.6,1836.4 ccw(c1302.5,1860.3) v1@1302.5,1826.5
  Bottom Layer w16: v1@1302.5,1798.5 cw(c1302.5,1764.7) 1326.4,1788.6 cw(c1350.3,1812.5) v1@1316.5,1812.5 ; v1(1302.5,1812.5) 1375,1740 1660,1740 v1(1715,1685) ; v1@1701,1685 ccw(c1667.2,1685) 1691.1,1708.9 ccw(c1715,1732.8) v1@1715,1699
GND: C1.2 C2.2 C3.2 C4.2 C6.1 C7.2 C9.1 C10.1 C11.1 ICSP1.6 ICSP.6 IOH1.7 L.C ON.C PC1.- PC2.- POWER.6 POWER.7 R3.1 RESET.1 RESET.2 RN1.7 RN2.5 S1.3 S1.4 S2.3 S2.4 S3.3 S3.4 S4.3 S4.4 U1.1 U2.2 U3.3 U3.33 U5.4 U10.8 X1.1 X1.3 Y2.2 ZU4.8 ZU4.22 | length 598.8
  Top Layer w11: U3.3@1590,2230 1590,2190 1615,2165
  Top Layer w12: U3.33@1573,2283 1590.47,2279.53 U3.3@1590.47,2228.54 ; POWER.6@2435,1060 POWER.7@2535,1060 ; POWER.6@2450.56,1044.44 cw(c2488.11,1006.89) 2488.11,1060 cw(c2488.11,1113.11) POWER.6@2450.56,1075.56 ; POWER.7@2519.44,1044.44 ccw(c2481.89,1006.89) 2481.89,1060 ccw(c2481.89,1113.11) POWER.7@2519.44,1075.56
  Bottom Layer w32: R3.1@1400,2620 1455,2675 ICSP1.6@1455,2730 ; ICSP1.6@1444.74,2719.74 cw(c1419.97,2694.97) 1455,2694.97 cw(c1490.03,2694.97) ICSP1.6@1465.26,2719.74
  other v1: 2735,1060 1681,1071 3602,1103 3427,1172 1985,1205 1477,1238 1285,1460 1451,1503 2456,1666 3520,1805 2860,1810 1745,1815 1310,1935 3175,2060 2691,2111 2020,2201 2541,2201 1616.53,2311.47 3410,2404 2026,2454 3381,2556 2571,2636 3461,2747 3949,2801 2898,2819 1245,2925 2555,2960
IO0: IOL.1 RN4.2 ZU4.2 | length 2277.5
  Top Layer w12: 3189.97,2274.25 cw(c3189.97,2201.51) v1@3242.13,2252.21 ; 3218.37,2274.25 cw(c3218.37,2229.12) v1@3250.74,2260.58 ; v1@3233.53,2243.85 ccw(c3161.57,2173.9) RN4.2@3161.57,2274.25 3225.75,2274.25 v1(3245,2255)
  Bottom Layer w16: 3167.32,1792.68 ccw(c3210,1835.36) ZU4.2@3210,1775 ; 3174.99,2270 cw(c3174.99,2184.99) 3235.1,2245.1 cw(c3211.2,2221.2) 3245,2221.2 cw(c3278.8,2221.2) v1@3254.9,2245.1 ; 3179.39,1780.61 cw(c3153.79,1755) ZU4.2@3190,1755 ; ZU4.2@3210,1755 3205,1755 3035,1925 3035,2115 3065,2145 3170,2145 3245,2220 v1(3245,2255) 3230,2270 3155,2270 3115,2310 3115,2360 3050,2425 3050,2730 3125,2805 3165,2805 3215,2855 3225,2855 3285,2915 3290,2915 IOL.1@3335,2960 ; 3213.62,2270 cw(c3213.62,2223.62) v1@3246.41,2256.41 ; 3292.5,2917.5 ccw(c3250.26,2959.75) IOL.1@3310,2959.94 ; 3304.39,2929.39 cw(c3330,2903.79) IOL.1@3330,2940
IO1: IOL.2 RN4.1 ZU4.3 | length 2102.2
  Top Layer w16: v1@3051.59,2194.41 cw(c3077.14,2168.86) 3077.14,2205 ; v1(3053,2193) 3065,2205 3145,2205 3161.57,2221.57 RN4.1@3161.57,2242.76 ; v1@3062.9,2183.1 cw(c3115.77,2130.23) 3115.77,2205
  Bottom Layer w16: 3018.49,2143.49 ccw(c2968.99,2193) v1@3039,2193 ; v1@3043.1,2202.9 ccw(c3014.37,2231.63) 3055,2231.63 ; 3045.81,2170.81 ccw(c3023.62,2193) v1@3055,2193 ; 3051.11,1848.89 cw(c2957.22,1755) ZU4.3@3090,1755 ; 3055,2221.97 ccw(c3081.97,2221.97) v1@3062.9,2202.9 ; 3078.42,1821.58 cw(c3011.85,1755) ZU4.3@3106,1755 ; ZU4.3@3099.85,1772.23 ccw(c3089.38,1790) 3110,1790 ; 3105.74,1794.26 cw(c3066.47,1755) ZU4.3@3122,1755 ; ZU4.3@3110,1755 3110,1790 ; ZU4.3@3120.15,1772.23 cw(c3130.62,1790) 3110,1790 ; 3192.5,2917.5 ccw(c3150.26,2959.75) IOL.2@3210,2959.94 ; 3204.39,2929.39 cw(c3230,2903.79) IOL.2@3230,2940 ; IOL.2@3235,2960 3190,2915 3190,2885 3145,2840 3105,2840 3015,2750 3015,2325 3055,2285 3055,2195 v1(3053,2193) 3055,2185 3055,2180 3006,2131 3006,1894 3110,1790
IO2: IOL.3 P1.1 ZU4.4 | length 2405.8
  Top Layer w10: IOL.3@3113.74,2943.74 cw(c3074.47,2904.47) 3130,2904.47 cw(c3185.53,2904.47) IOL.3@3146.26,2943.74 ; IOL.3@3120.81,2950.81 cw(c3098.62,2928.62) 3130,2928.62 cw(c3161.38,2928.62) IOL.3@3139.19,2950.81 ; IOL.3@3130,2960 3130,2903 3233,2800 P1.1@3690,2800 ; P1.1@3671.96,2781.96 ccw(c3628.41,2738.41) 3628.41,2800 ccw(c3628.41,2861.59) P1.1@3671.96,2818.04 ; P1.1@3679.03,2789.03 ccw(c3652.55,2762.55) 3652.55,2800 ccw(c3652.55,2837.45) P1.1@3679.03,2810.97
  Bottom Layer w16: ZU4.4@2995.86,1769.14 ccw(c2961.72,1803.28) 3010,1803.28 ccw(c3058.28,1803.28) ZU4.4@3024.14,1769.14 ; ZU4.4@3010,1755 3010,1820 2970,1860 2970,2135 2995,2160 2995,2300 2980,2315 2980,2770 3085,2875 3085,2910 IOL.3@3135,2960 ; 3092.32,2917.32 ccw(c3049.64,2960) IOL.3@3110,2960 ; 3104.39,2929.39 cw(c3130,2903.79) IOL.3@3130,2940
IO3: IOL.4 P1.3 ZU4.5 | length 2518.8
  Top Layer w10: IOL.4@3013.74,2943.74 cw(c2974.47,2904.47) 3030,2904.47 cw(c3085.53,2904.47) IOL.4@3046.26,2943.74 ; IOL.4@3020.81,2950.81 cw(c2998.62,2928.62) 3030,2928.62 cw(c3061.38,2928.62) IOL.4@3039.19,2950.81 ; IOL.4@3030,2960 3030,2869 3199,2700 P1.3@3690,2700 ; P1.3@3671.96,2681.96 ccw(c3628.41,2638.41) 3628.41,2700 ccw(c3628.41,2761.59) P1.3@3671.96,2718.04 ; P1.3@3679.03,2689.03 ccw(c3652.55,2662.55) 3652.55,2700 ccw(c3652.55,2737.45) P1.3@3679.03,2710.97
  Bottom Layer w16: ZU4.5@2910,1755 2910,1775 2935,1800 ; ZU4.5@2913.65,1756.64 cw(c2935.66,1766.53) 2918.6,1783.6 ; ZU4.5@2928.24,1763.2 cw(c2958.3,1776.7) 2935,1800 ; IOL.4@3015.86,2945.86 cw(c2969.64,2899.64) 3035,2899.64 ; 3035,2923.79 cw(c3066.21,2923.79) IOL.4@3044.14,2945.86 ; IOL.4@3035,2960 3035,2880 2945,2790 2945,2305 2950,2300 2950,2175 2935,2160 2935,1800
IO4: IOL.5 P1.5 ZU4.6 | length 2730
  Top Layer w10: IOL.5@2913.74,2943.74 cw(c2874.47,2904.47) 2930,2904.47 cw(c2985.53,2904.47) IOL.5@2946.26,2943.74 ; IOL.5@2920.81,2950.81 cw(c2898.62,2928.62) 2930,2928.62 cw(c2961.38,2928.62) IOL.5@2939.19,2950.81 ; IOL.5@2930,2960 2930,2851 3181,2600 P1.5@3690,2600 ; P1.5@3671.96,2581.96 ccw(c3628.41,2538.41) 3628.41,2600 ccw(c3628.41,2661.59) P1.5@3671.96,2618.04 ; P1.5@3679.03,2589.03 ccw(c3652.55,2562.55) 3652.55,2600 ccw(c3652.55,2637.45) P1.5@3679.03,2610.97
  Bottom Layer w16: ZU4.6@2795.86,1769.14 ccw(c2761.72,1803.28) 2810,1803.28 ccw(c2858.28,1803.28) ZU4.6@2824.14,1769.14 ; ZU4.6@2810,1755 2810,2015 2795,2030 2795,2805 2930,2940 IOL.5@2935,2960 ; 2881.72,2891.72 ccw(c2813.43,2960) IOL.5@2910,2960 ; 2909.03,2919.03 ccw(c2868.06,2960) IOL.5@2926,2960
